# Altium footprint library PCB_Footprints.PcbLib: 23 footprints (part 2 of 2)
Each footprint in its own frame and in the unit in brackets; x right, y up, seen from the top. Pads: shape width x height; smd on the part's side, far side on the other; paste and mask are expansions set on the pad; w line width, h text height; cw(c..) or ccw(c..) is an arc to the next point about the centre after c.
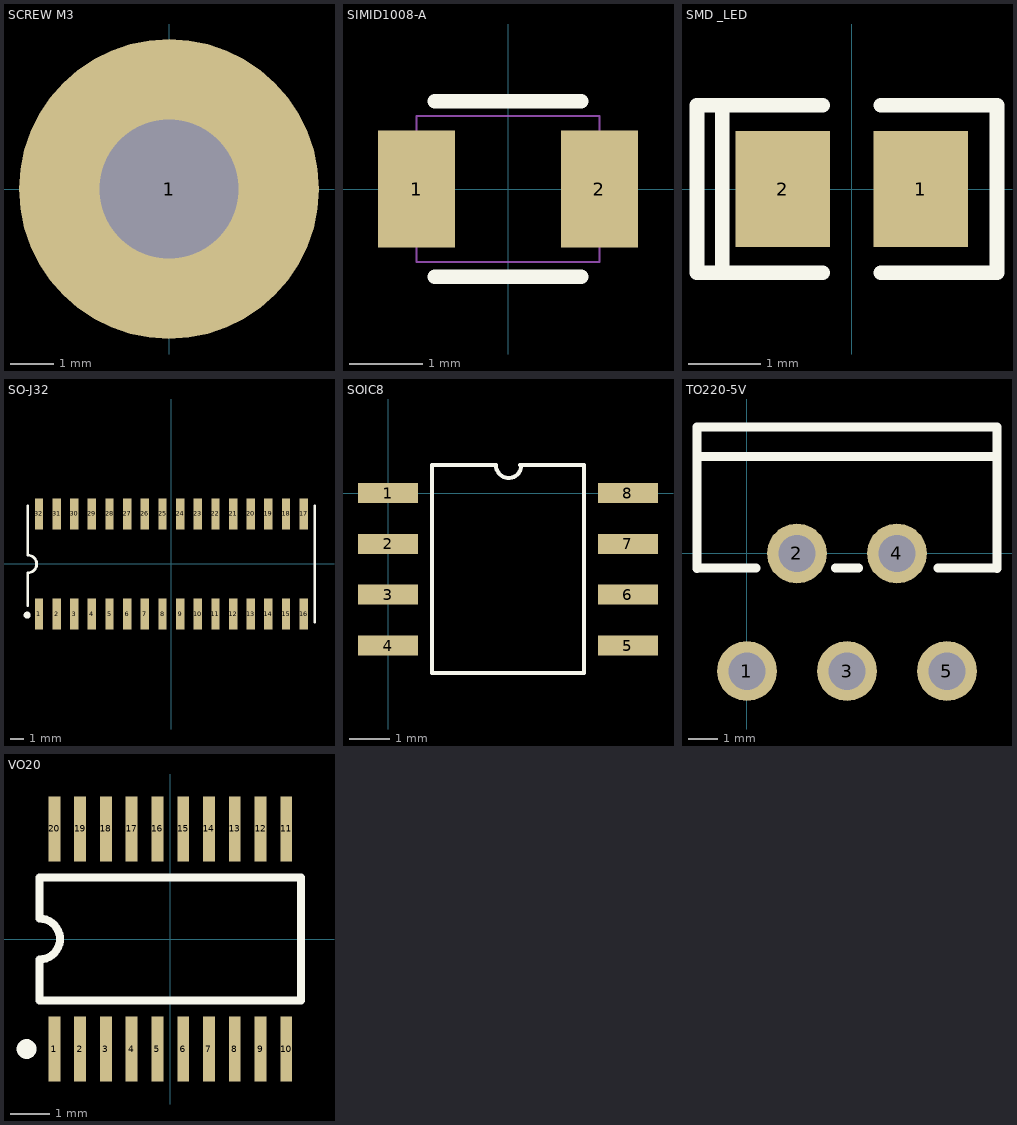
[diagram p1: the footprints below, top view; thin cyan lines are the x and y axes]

## SCREW M3 [mil]
pads (1):
  round 270 hole 125: 1(0,0)

## SIMID1008-A [mm]
pads (2):
  rect 1.05x1.6 smd: 1(-1.25,0) 2(1.25,0)
Top Overlay:
  lines w0.2: -1,-1.2 1,-1.2 ; -1,1.2 1,1.2
Mechanical 15:
  lines w0.025: -1.25,-1 -1.25,1 1.25,1 1.25,-1 -1.25,-1

## SMD _LED [mm]
pads (2):
  rect 1.3x1.6 smd: 1(0.95,0) 2(-0.95,0)
Top Overlay:
  lines w0.2: -1.78,-1.15 -1.78,1.15 ; -0.4,-1.15 -2.13,-1.15 -2.13,1.15 -0.4,1.15 ; 0.4,-1.15 2,-1.15 2,1.15 0.4,1.15

## SO-J32 [mm]
pads (32):
  rect 0.6x2.2 smd: 1(-9.525,-3.6) 2(-8.255,-3.6) 3(-6.985,-3.6) 4(-5.715,-3.6) 5(-4.445,-3.6) 6(-3.175,-3.6) 7(-1.905,-3.6) 8(-0.635,-3.6) 9(0.635,-3.6) 10(1.905,-3.6) 11(3.175,-3.6) 12(4.445,-3.6) 13(5.715,-3.6) 14(6.985,-3.6) 15(8.255,-3.6) 16(9.525,-3.6) 17(9.525,3.6) 18(8.255,3.6) 19(6.985,3.6) 20(5.715,3.6) 21(4.445,3.6) 22(3.175,3.6) 23(1.905,3.6) 24(0.635,3.6) 25(-0.635,3.6) 26(-1.905,3.6) 27(-3.175,3.6) 28(-4.445,3.6) 29(-5.715,3.6) 30(-6.985,3.6) 31(-8.255,3.6) 32(-9.525,3.6)
Top Overlay:
  circle w0.25: c-10.375,-3.676 r0.125
  lines w0.2: -10.325,-2.996 -10.325,-0.635 ccw(c-10.325,0) -10.325,0.635 -10.325,4.191 ; 10.325,-4.191 10.325,4.191

## SOIC8 [mm]
pads (8):
  rect 1.5x0.5 smd: 1(0,0) 2(0,-1.27) 3(0,-2.54) 4(0,-3.81) 5(6,-3.81) 6(6,-2.54) 7(6,-1.27) 8(6,0)
Top Overlay:
  lines w0.1: 3.3,0.7 4.9,0.7 4.9,-4.5 1.1,-4.5 1.1,0.7 2.7,0.7 ccw(c3.017,0.7) 3.335,0.7

## TO220-5V [mil] "TO220 5-lead, molded, stagger bend package."
height 708.66
pads (5):
  round 80 hole 50: 1(0,-157.48) 2(66.93,0) 3(133.86,-157.48) 4(200.79,0) 5(267.72,-157.48)
Top Overlay:
  lines w12: -66.93,-20.08 -66.93,129.92 ; -66.93,-19.68 11.81,-19.68 ; -66.93,129.29 -66.93,169.29 ; -65.35,129.92 334.65,129.92 334.65,-20.08 ; -65.35,169.29 334.65,169.29 334.65,129.29 ; 118.11,-19.68 149.61,-19.68 ; 255.91,-19.68 334.65,-19.68

## VO20 [mm]
pads (20):
  rect 0.3x1.65 smd: 1(-2.925,-2.775) 2(-2.275,-2.775) 3(-1.625,-2.775) 4(-0.975,-2.775) 5(-0.325,-2.775) 6(0.325,-2.775) 7(0.975,-2.775) 8(1.625,-2.775) 9(2.275,-2.775) 10(2.925,-2.775) 11(2.925,2.775) 12(2.275,2.775) 13(1.625,2.775) 14(0.975,2.775) 15(0.325,2.775) 16(-0.325,2.775) 17(-0.975,2.775) 18(-1.625,2.775) 19(-2.275,2.775) 20(-2.925,2.775)
Top Overlay:
  circle w0.25: c-3.625,-2.775 r0.125
  lines w0.2: -3.3,-1.55 3.3,-1.55 3.3,1.55 -3.3,1.55 -3.3,0.517 cw(c-3.3,0) -3.3,-0.517 -3.3,-1.55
